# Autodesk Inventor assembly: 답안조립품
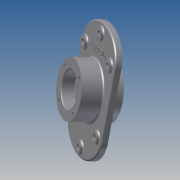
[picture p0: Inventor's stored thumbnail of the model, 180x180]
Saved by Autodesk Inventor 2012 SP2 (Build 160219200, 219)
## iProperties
Created: 2015-02
Part Number: 답안조립품
Document SubType Name: Assembly
Designer: Administrator
Author: Administrator
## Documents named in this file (2)
- C:\Users\Administrator\Desktop\450208V1003\450208V1003\답안조립품.iam
- C:\Users\Administrator\Desktop\450208V1003\450208V1003\본체-1.ipt
